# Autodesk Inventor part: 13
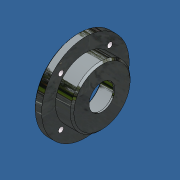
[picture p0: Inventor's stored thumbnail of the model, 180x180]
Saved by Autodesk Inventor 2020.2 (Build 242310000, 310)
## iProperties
Created: 2016-09
Part Number: 13
Material: Steel
Document SubType Name: Modeling
Designer: Mike Taylor
Mass: 507.816 g
Surface Area: 225.486 cm^2
Volume: 64.6899 cm^3
Density: 7.85 g/cm^3
Appearance: Plate
Translation Standard: STEP AP214IS
FileName: 29_5060_0_1.stp
PreProcessor: ACIS
PostProcessor: Build: 160, Release: 2012 RTM - Date: Tue 03/01/2011
Sent Units: centimeter
Uncertainty: 0.0
Author: Mike Taylor
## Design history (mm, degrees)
node "131"
sketch "Sketch1"
  geometry: L1 (45.5, 0)-(45.5, -190) reference; L2 (0, -235.5)-(-170, -235.5) reference; L3 (-215.5, -190)-(-215.5, 0) reference; L4 (-170, 45.5)-(0, 45.5) reference; L5 (-65.14, -134.64)-(-65.14, -99.64) reference; L6 (-74.14, -99.64)-(-74.14, -134.64) reference; L7 (-65.14, -205.35)-(-65.14, -170.35) reference; L8 (-74.14, -170.35)-(-74.14, -205.35) reference; L9 (-135.85, -134.64)-(-135.85, -99.64) reference; L10 (-144.85, -99.64)-(-144.85, -134.64) reference; L11 (-135.85, -205.35)-(-135.85, -170.35) reference; L12 (-144.85, -170.35)-(-144.85, -205.35) reference; L13 (-85, -170)-(-85, -135) reference; L14 (-125, -135)-(-125, -170) reference; C1 r 2.5 at (-175.495, -22.496) reference; C2 r 2.5 at (26.517, 26.517) reference; C3 r 2.5 at (26.517, -26.516) reference; C4 r 2.5 at (-26.517, 26.517) reference; C5 r 2.5 at (-26.517, -26.516) reference; C6 r 33.5 at (0, 0) reference; C7 r 4.25 at (-75.5, 22.5) reference; C8 r 4.25 at (-75.5, -22.5) reference; C9 r 4.25 at (-195.5, 22.5) reference; C10 r 4.25 at (-195.5, -22.5) reference; C11 r 2.5 at (-95.495, -22.496) reference; A1 r 45.5 centre (0, -190) between (0, -235.5) and (45.5, -190) reference; A2 r 45.5 centre (-170, -190) between (-215.5, -190) and (-170, -235.5) reference; A3 r 45.5 centre (-170, 0) between (-170, 45.5) and (-215.5, 0) reference; A4 r 45.5 centre (0, 0) between (45.5, 0) and (0, 45.5) reference; A5 r 4.5 centre (-69.64, -134.64) between (-74.14, -134.64) and (-65.14, -134.64) reference; A6 r 4.5 centre (-69.64, -99.64) between (-65.14, -99.64) and (-74.14, -99.64) reference; A7 r 4.5 centre (-69.64, -205.35) between (-74.14, -205.35) and (-65.14, -205.35) reference; A8 r 4.5 centre (-69.64, -170.35) between (-65.14, -170.35) and (-74.14, -170.35) reference; A9 r 4.5 centre (-140.35, -134.64) between (-144.85, -134.64) and (-135.85, -134.64) reference; A10 r 4.5 centre (-140.35, -99.64) between (-135.85, -99.64) and (-144.85, -99.64) reference; A11 r 4.5 centre (-140.35, -205.35) between (-144.85, -205.35) and (-135.85, -205.35) reference; A12 r 4.5 centre (-140.35, -170.35) between (-135.85, -170.35) and (-144.85, -170.35) reference; A13 r 20 centre (-105, -170) between (-125, -170) and (-85, -170) reference; A14 r 20 centre (-105, -135) between (-85, -135) and (-125, -135) reference; 5 further points
  constraints: 4 coincident
hole "Hole1" sketch "Sketch1" at (-26.517, 26.517), (26.517, 26.517), (26.517, -26.516), (-26.517, -26.516) diameter "d0" = 5.5; stored, may be unused: countersink angle "d4" = 90 deg, drill point angle "d6" = 118 deg; dims "d1" = 6, "d2" = 10, "d3" = 3.7, "d5" = 8
node "13"
node "Base1"
node "Reference1"
